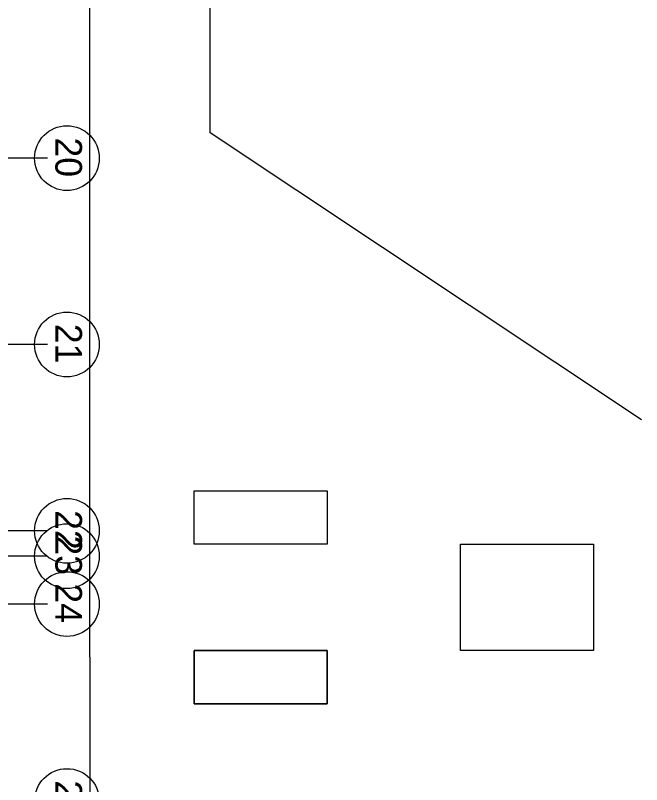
# Model space of a CAD drawing. Extents: x -264165 to -263575, y -1242333 to -1242036.
# Drawn here: x -263788.69 to -263765.16, y -1242233.41 to -1242204.52 of the extents above; entities that cross this region are included whole.
import ezdxf

# ---------------------------------------------------------------- set-up
doc = ezdxf.new("R2010")
doc.units = 0
doc.layers.add('KFA_HESCON_OSI_STAVBY', color=7, linetype='Continuous')
doc.layers.add('KFA_SITUACIA_DRS_VYTYCOVAK_SEDA', color=7, linetype='Continuous')

msp = doc.modelspace()

# ---------------------------------------------------------------- linework, layer by layer
at = {"layer": 'KFA_HESCON_OSI_STAVBY'}
for p, q in [((-263787.486, -1242209.882), (-263921.823, -1242209.882)), ((-263787.486, -1242209.882), (-263787.486, -1242209.882)), ((-263787.486, -1242216.882), (-263921.823, -1242216.882)), ((-263787.486, -1242216.882), (-263787.486, -1242216.882)), ((-263787.486, -1242223.882), (-263921.823, -1242223.882)), ((-263787.486, -1242223.882), (-263787.486, -1242223.882)), ((-263787.486, -1242224.832), (-263921.823, -1242224.832)), ((-263787.486, -1242224.832), (-263787.486, -1242224.832)), ((-263787.486, -1242226.632), (-263921.823, -1242226.632)), ((-263787.486, -1242226.632), (-263787.486, -1242226.632))]:
    msp.add_line(p, q, dxfattribs=at)
for centre in [(-263786.751, -1242209.882), (-263786.751, -1242216.882), (-263786.751, -1242223.882), (-263786.751, -1242224.832), (-263786.751, -1242226.632), (-263786.751, -1242234.032)]:
    msp.add_circle(centre, 1.216, dxfattribs=at)
at = {"layer": 'KFA_SITUACIA_DRS_VYTYCOVAK_SEDA'}
for p, q in [((-263781.364, -1242208.936), (-263781.371, -1242084.903)), ((-263781.364, -1242208.936), (-263781.371, -1242084.903)), ((-263785.893, -1242228.625), (-263785.893, -1242090.308)), ((-263765.158, -1242219.708), (-263781.364, -1242208.936)), ((-263765.158, -1242219.709), (-263781.364, -1242208.936)), ((-263781.968, -1242222.382), (-263776.968, -1242222.382)), ((-263781.968, -1242224.382), (-263781.968, -1242222.382)), ((-263781.968, -1242222.382), (-263776.968, -1242222.382)), ((-263781.968, -1242224.382), (-263781.968, -1242222.382)), ((-263776.968, -1242222.382), (-263776.968, -1242224.382)), ((-263776.968, -1242222.382), (-263776.968, -1242224.382)), ((-263776.968, -1242224.382), (-263781.968, -1242224.382)), ((-263776.968, -1242224.382), (-263781.968, -1242224.382)), ((-263771.968, -1242224.382), (-263766.968, -1242224.382)), ((-263771.968, -1242228.382), (-263771.968, -1242224.382)), ((-263771.968, -1242224.382), (-263766.968, -1242224.382)), ((-263771.968, -1242228.382), (-263771.968, -1242224.382)), ((-263766.968, -1242224.382), (-263766.968, -1242228.382)), ((-263766.968, -1242224.382), (-263766.968, -1242228.382)), ((-263785.893, -1242228.625), (-263785.893, -1242238.458)), ((-263781.968, -1242230.382), (-263781.968, -1242228.382)), ((-263781.968, -1242228.382), (-263776.968, -1242228.382)), ((-263781.968, -1242228.382), (-263781.968, -1242230.382)), ((-263776.968, -1242228.382), (-263781.968, -1242228.382)), ((-263776.968, -1242228.382), (-263776.968, -1242230.382)), ((-263776.968, -1242230.382), (-263776.968, -1242228.382)), ((-263766.968, -1242228.382), (-263771.968, -1242228.382)), ((-263766.968, -1242228.382), (-263771.968, -1242228.382)), ((-263776.968, -1242230.382), (-263781.968, -1242230.382)), ((-263781.968, -1242230.382), (-263776.968, -1242230.382))]:
    msp.add_line(p, q, dxfattribs=at)

# ---------------------------------------------------------------- texts
at = {"layer": 'KFA_HESCON_OSI_STAVBY'}
for s, p in [('20', (-263787.186, -1242209.105)), ('21', (-263787.186, -1242216.105)), ('22', (-263787.186, -1242223.105)), ('23', (-263787.186, -1242224.055)), ('24', (-263787.186, -1242225.855)), ('25', (-263787.186, -1242233.255))]:
    msp.add_text(s, height=1, rotation=270, dxfattribs=at).set_placement(p)

doc.saveas('drawing.dxf')
